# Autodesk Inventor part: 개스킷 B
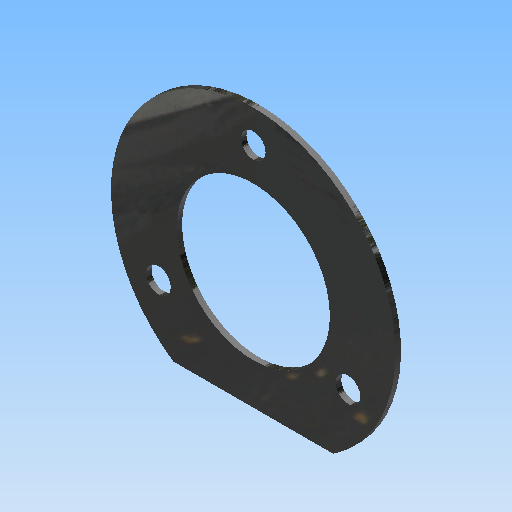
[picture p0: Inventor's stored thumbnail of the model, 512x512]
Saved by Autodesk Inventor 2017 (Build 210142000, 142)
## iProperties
Created: 2020-04
Part Number: 개스킷 B
Material: 고무
Document SubType Name: Modeling
Designer: mduedu
Density: 0.93 g/cm^3
Appearance: 고무 - 검은색 - 버전 1.1
Mass: 1.27493 g
Surface Area: 30.3371 cm^2
Volume: 1.37089 cm^3
Author: mduedu
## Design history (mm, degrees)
sketch "스케치1"
  geometry: C1 r 26 at (0, 0); 1 further point
  constraints: 1 centre point, 1 coincident
  dimensions: "d0" = 52 diameter of C1
extrude "돌출1" new body sketch "스케치1" distance "d1" = 1; taper "d2" = 0 deg
sketch "스케치2"
  geometry: L1 (-14.62, -21.5)-(14.62, -21.5); A1 r 26 centre (0, 0) between (-14.62, -21.5) and (14.62, -21.5) reference; 1 further point
  constraints: 2 end point, 2 point on circle, 1 horizontal
  dimensions: "d3" = 21.5 distance from line of L1 point (0, 0)
extrude "돌출2" cut sketch "스케치2" stored distance "d4" = 1; taper "d5" = 0 deg
sketch "스케치3" dims "d6" = 40
  geometry: 3 further points
  constraints: 2 vertical alignment, 1 coincident, 2 other
hole "구멍1" sketch "스케치3" at (0, 20) diameter "d7" = 4.5; stored, may be unused: countersink angle "d11" = 90 deg, drill point angle "d13" = 118 deg; dims "d8" = 6, "d9" = 4, "d10" = 2, "d12" = 8
sketch "스케치4"
  geometry: C1 r 14 at (0, 0); 1 further point
  constraints: 1 centre point, 1 coincident
  dimensions: "d17" = 28 diameter of C1
extrude "돌출3" cut sketch "스케치4" stored distance "d18" = 1; taper "d19" = 0 deg
node "솔리드1"
pattern_circular "원형 패턴1" dims angle "d15" = 360 deg
node "투영된 루프1"
